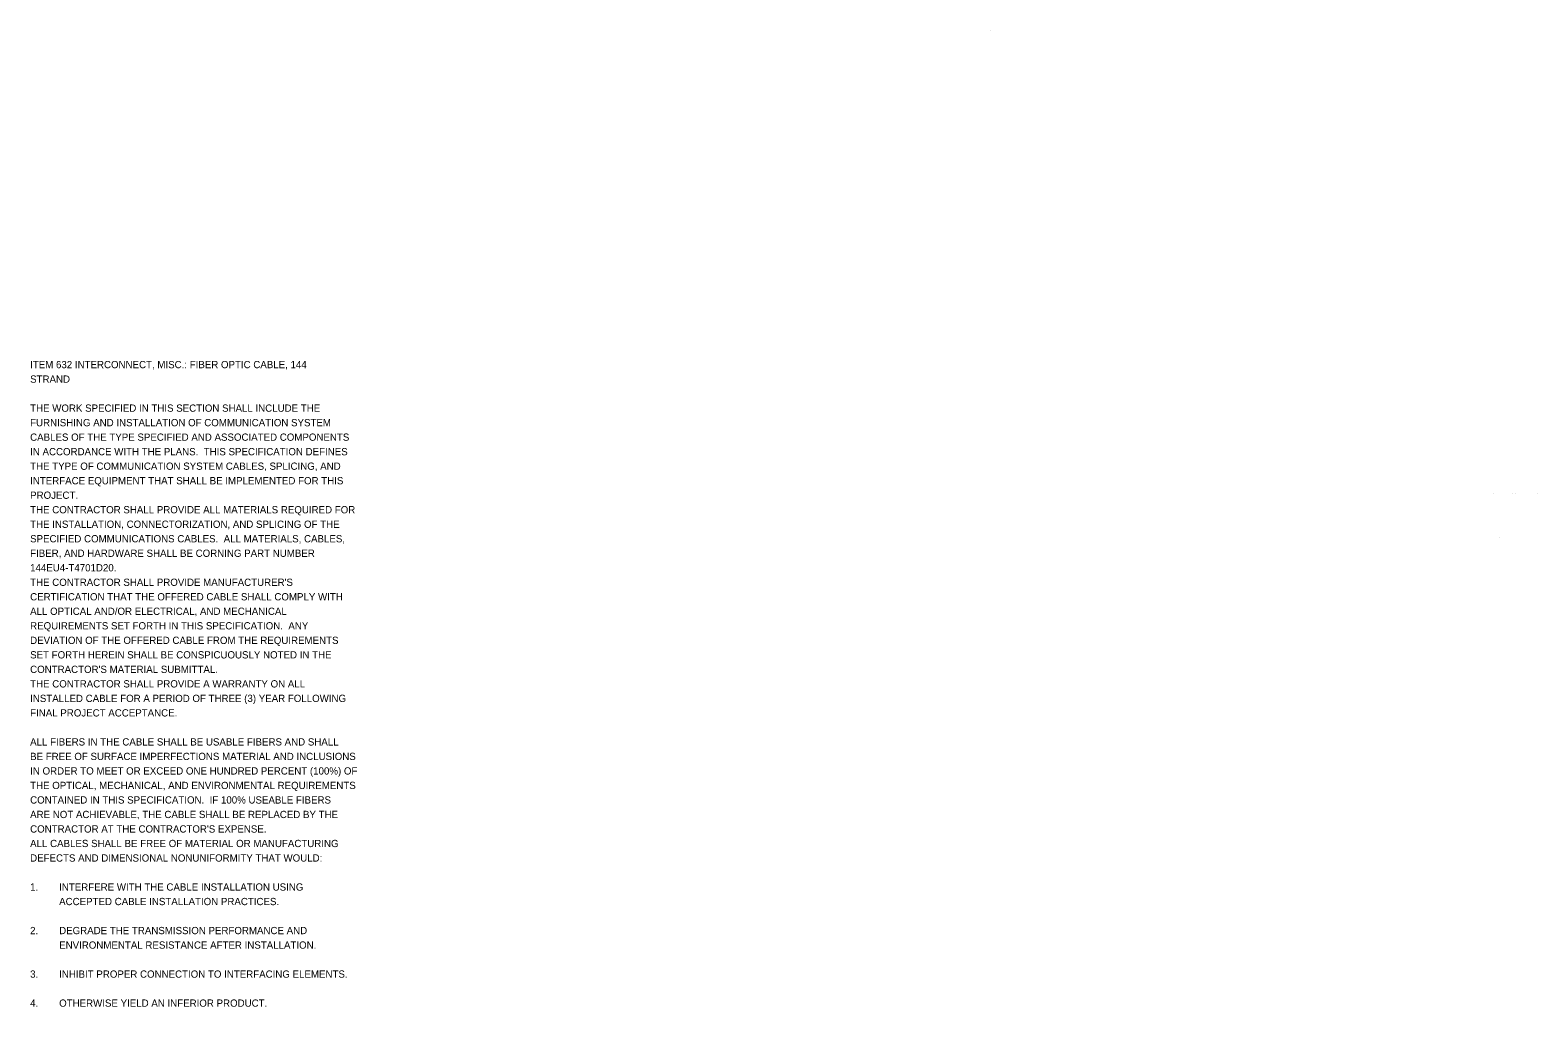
# Model space of a CAD drawing. Extents: x -15.1 to 53.7, y -46.4 to 36.
# Drawn here: x 24.65 to 53.74, y -28.01 to -9.17 of the extents above; entities that cross this region are included whole.
import ezdxf

# ---------------------------------------------------------------- set-up
doc = ezdxf.new("R2010")
doc.units = 0
for name, color, linetype in [('Default', 7, 'Continuous'), ('SH_Data', 7, 'Continuous'), ('SH_Text', 7, 'Continuous')]:
    doc.layers.add(name, color=color, linetype=linetype)

# ---------------------------------------------------------------- blocks, each defined once
blk = doc.blocks.new('POINT_DISPLAY')
at = {"layer": 'Default'}
blk.add_line((0, 0), (0, 0), dxfattribs=at)

msp = doc.modelspace()

# ---------------------------------------------------------------- block references
at = {"layer": 'Default', "xscale": 3.9370000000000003, "yscale": 3.9370000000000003}
for p in [(43.185, -9.166), (52.888, -18.102), (52.888, -18.102), (53.254, -18.102), (53.316, -18.102), (53.743, -18.102), (53.01, -18.957)]:
    msp.add_blockref('POINT_DISPLAY', p, dxfattribs=at)

# ---------------------------------------------------------------- texts
at = {"layer": 'SH_Data'}
for s, p in [('ITEM 632 INTERCONNECT, MISC.: FIBER OPTIC CABLE, 144 ', (24.654, -15.689)), ('STRAND', (24.654, -15.969))]:
    msp.add_text(s, height=0.14, dxfattribs=at).set_placement(p)
at = {"layer": 'SH_Text'}
for s, p in [('THE WORK SPECIFIED IN THIS SECTION SHALL INCLUDE THE ', (24.654, -16.529)), ('FURNISHING AND INSTALLATION OF COMMUNICATION SYSTEM ', (24.654, -16.809)), ('CABLES OF THE TYPE SPECIFIED AND ASSOCIATED COMPONENTS ', (24.654, -17.089)), ('IN ACCORDANCE WITH THE PLANS.  THIS SPECIFICATION DEFINES ', (24.654, -17.369)), ('THE TYPE OF COMMUNICATION SYSTEM CABLES, SPLICING, AND ', (24.654, -17.649)), ('INTERFACE EQUIPMENT THAT SHALL BE IMPLEMENTED FOR THIS ', (24.654, -17.929)), ('PROJECT.', (24.654, -18.209)), ('THE CONTRACTOR SHALL PROVIDE ALL MATERIALS REQUIRED FOR ', (24.654, -18.489)), ('THE INSTALLATION, CONNECTORIZATION, AND SPLICING OF THE ', (24.654, -18.769)), ('SPECIFIED COMMUNICATIONS CABLES.  ALL MATERIALS, CABLES, ', (24.654, -19.049)), ('FIBER, AND HARDWARE SHALL BE CORNING PART NUMBER ', (24.654, -19.329)), ('144EU4-T4701D20.', (24.654, -19.609)), ("THE CONTRACTOR SHALL PROVIDE MANUFACTURER'S ", (24.654, -19.889)), ('CERTIFICATION THAT THE OFFERED CABLE SHALL COMPLY WITH ', (24.654, -20.169)), ('ALL OPTICAL AND/OR ELECTRICAL, AND MECHANICAL ', (24.654, -20.449)), ('REQUIREMENTS SET FORTH IN THIS SPECIFICATION.  ANY ', (24.654, -20.729)), ('DEVIATION OF THE OFFERED CABLE FROM THE REQUIREMENTS ', (24.654, -21.009)), ('SET FORTH HEREIN SHALL BE CONSPICUOUSLY NOTED IN THE ', (24.654, -21.289)), ("CONTRACTOR'S MATERIAL SUBMITTAL. ", (24.654, -21.569)), ('THE CONTRACTOR SHALL PROVIDE A WARRANTY ON ALL ', (24.654, -21.849)), ('INSTALLED CABLE FOR A PERIOD OF THREE (3) YEAR FOLLOWING ', (24.654, -22.129)), ('FINAL PROJECT ACCEPTANCE. ', (24.654, -22.409)), ('ALL FIBERS IN THE CABLE SHALL BE USABLE FIBERS AND SHALL ', (24.654, -22.969)), ('BE FREE OF SURFACE IMPERFECTIONS MATERIAL AND INCLUSIONS ', (24.654, -23.249)), ('IN ORDER TO MEET OR EXCEED ONE HUNDRED PERCENT (100%) OF ', (24.654, -23.529)), ('THE OPTICAL, MECHANICAL, AND ENVIRONMENTAL REQUIREMENTS ', (24.654, -23.809)), ('CONTAINED IN THIS SPECIFICATION.  IF 100% USEABLE FIBERS ', (24.654, -24.089)), ('ARE NOT ACHIEVABLE, THE CABLE SHALL BE REPLACED BY THE ', (24.654, -24.369)), ("CONTRACTOR AT THE CONTRACTOR'S EXPENSE.", (24.654, -24.649)), ('ALL CABLES SHALL BE FREE OF MATERIAL OR MANUFACTURING ', (24.654, -24.929)), ('DEFECTS AND DIMENSIONAL NONUNIFORMITY THAT WOULD:', (24.654, -25.209)), ('1.', (24.654, -25.769)), ('INTERFERE WITH THE CABLE INSTALLATION USING ', (25.214, -25.769)), ('ACCEPTED CABLE INSTALLATION PRACTICES.', (25.214, -26.049)), ('2.', (24.654, -26.609)), ('DEGRADE THE TRANSMISSION PERFORMANCE AND ', (25.214, -26.609)), ('ENVIRONMENTAL RESISTANCE AFTER INSTALLATION.', (25.214, -26.889)), ('3.', (24.654, -27.449)), ('INHIBIT PROPER CONNECTION TO INTERFACING ELEMENTS.', (25.214, -27.449)), ('4.', (24.654, -28.009)), ('OTHERWISE YIELD AN INFERIOR PRODUCT.', (25.214, -28.009))]:
    msp.add_text(s, height=0.14, rotation=360, dxfattribs=at).set_placement(p)

doc.saveas('drawing.dxf')
